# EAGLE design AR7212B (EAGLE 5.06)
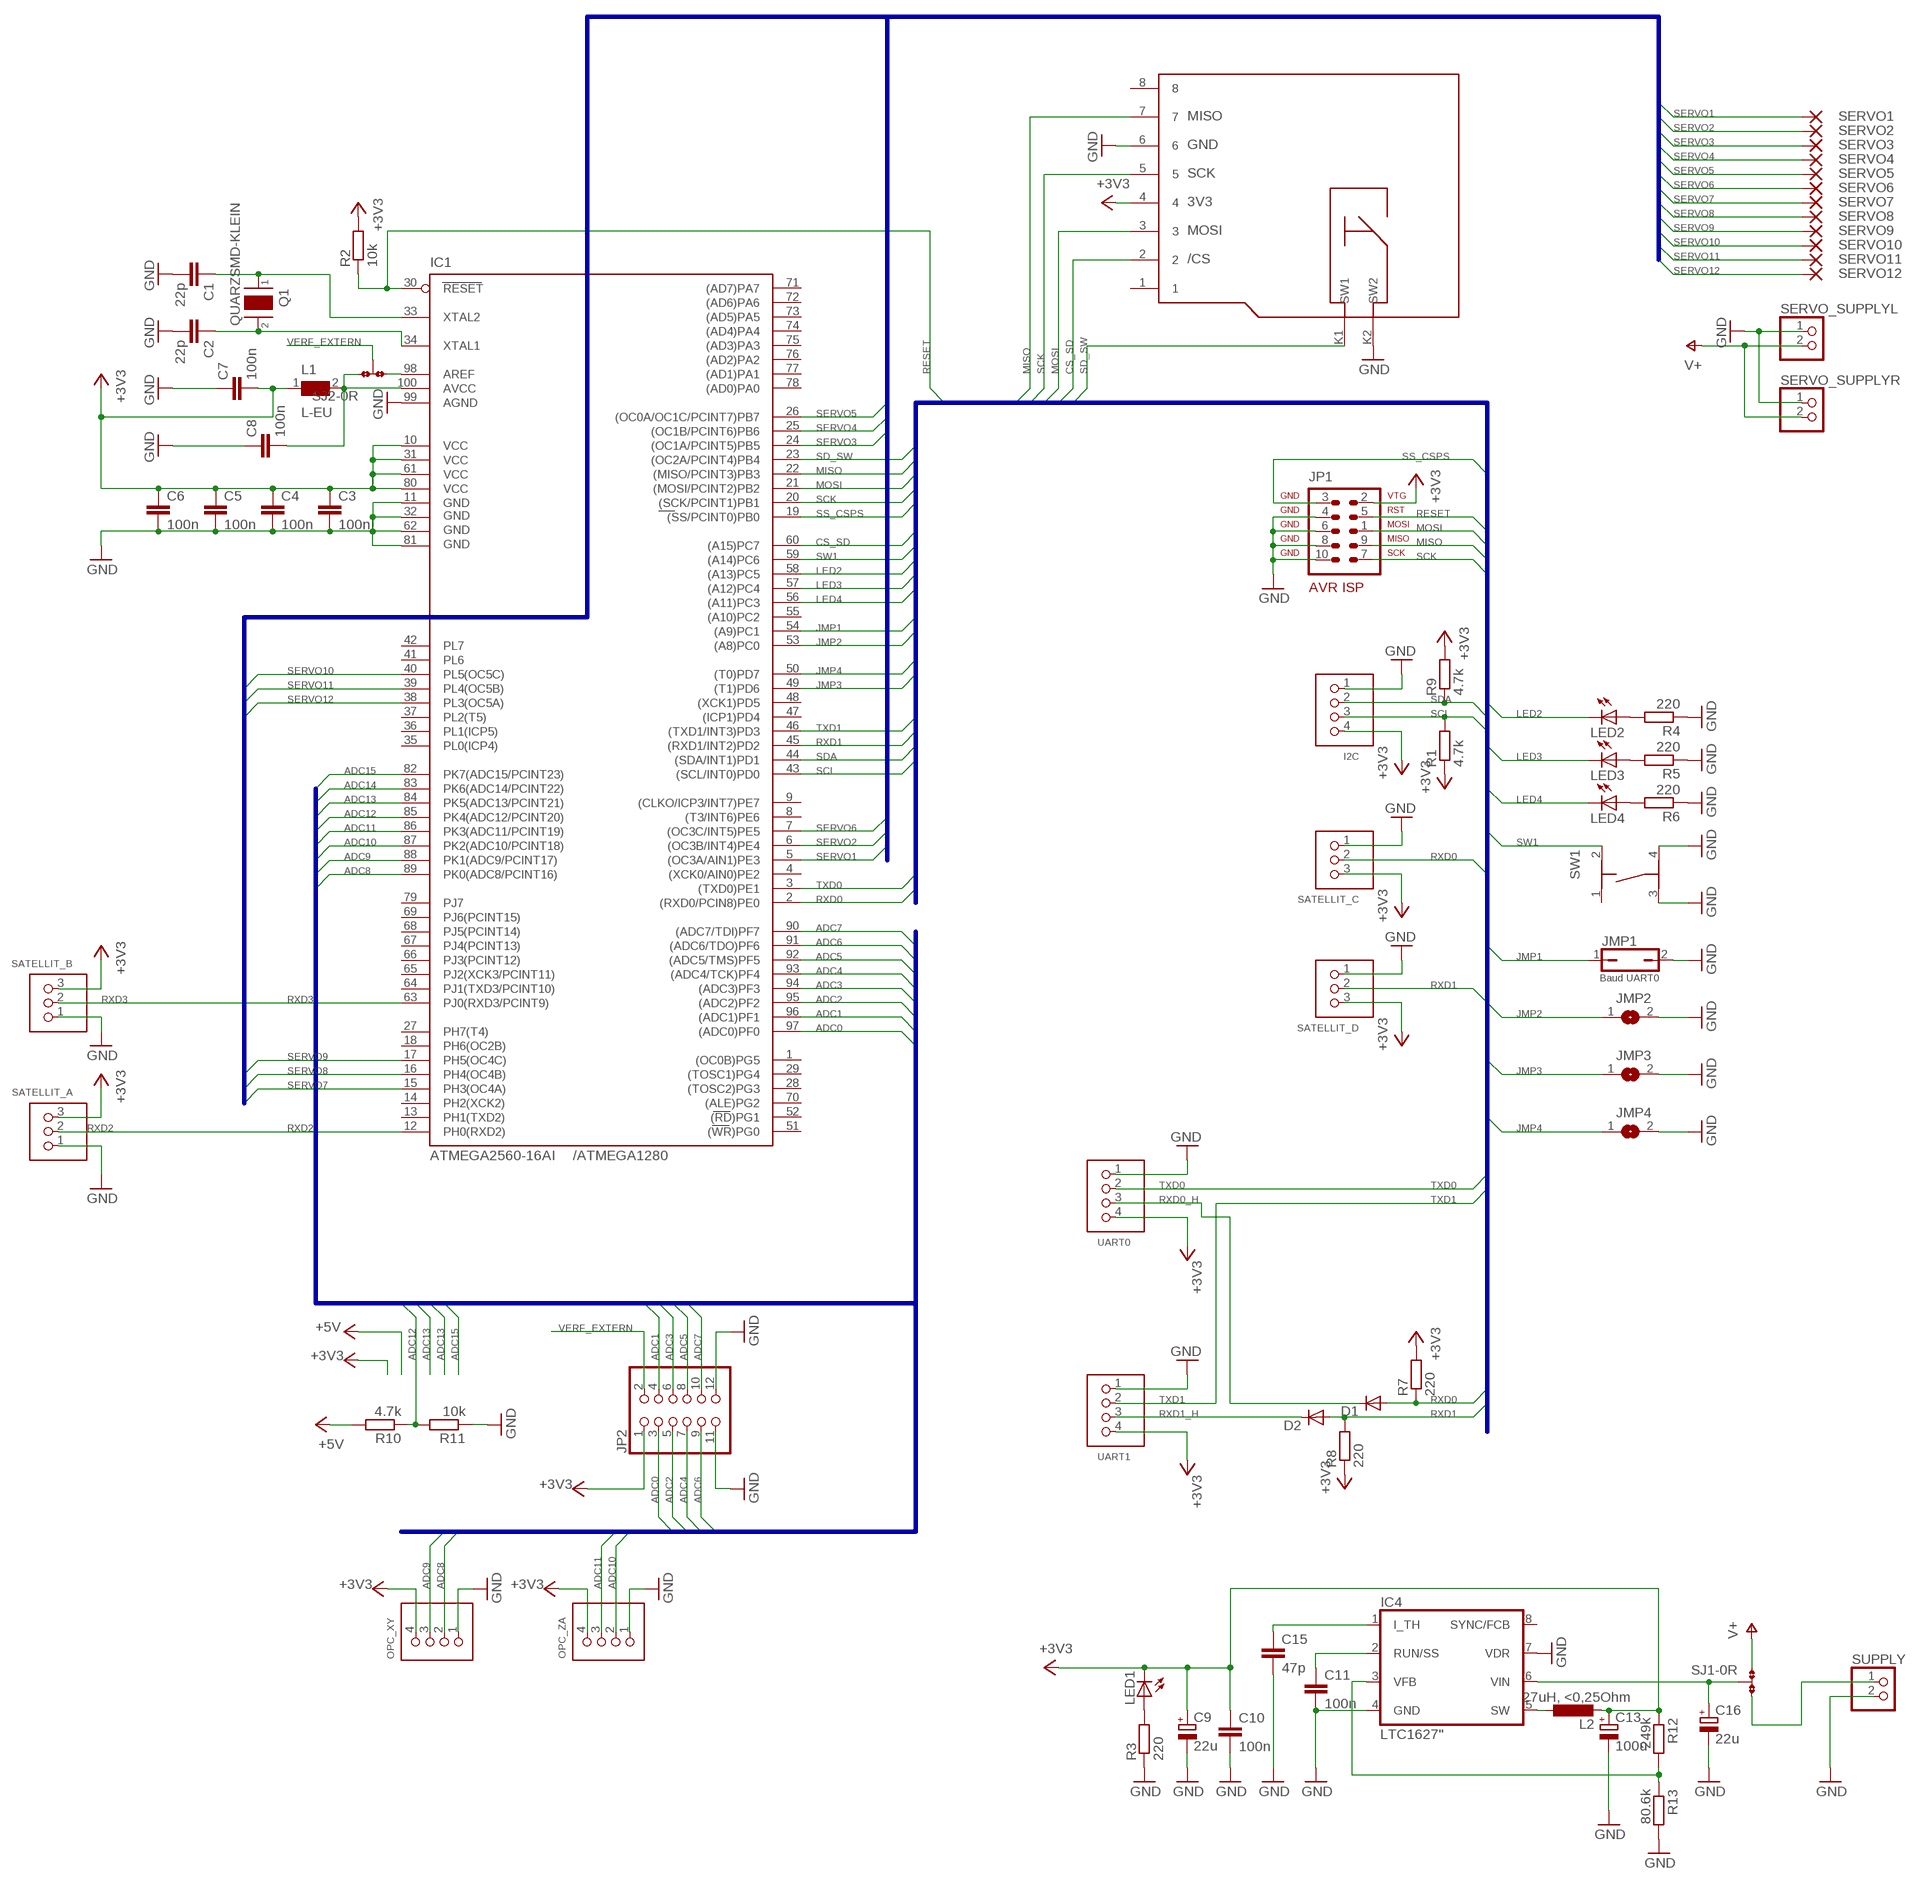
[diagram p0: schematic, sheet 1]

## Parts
C1  22p  C-EUC0805  [C0805]
C2  22p  C-EUC0805  [C0805]
C3  100n  C-EUC0805  [C0805]
C4  100n  C-EUC0805  [C0805]
C5  100n  C-EUC0805  [C0805]
C6  100n  C-EUC0805  [C0805]
C7  100n  C-EUC0805  [C0805]
C8  100n  C-EUC0805  [C0805]
C9  22u  CPOL-EU085CS-1AR  [085CS_1AR]
C10  100n  C-EUC0805  [C0805]
C11  100n  C-EUC0805  [C0805]
C13  100u  CPOL-EU085CS-1AR  [085CS_1AR]
C15  47p  C-EUC0805  [C0805]
C16  22u  CPOL-EU085CS-1AR  [085CS_1AR]
D1  DIODE-MINIMELF  [MINIMELF]
D2  DIODE-MINIMELF  [MINIMELF]
I2C  4PINS  [S4B-ZR-3.4]
IC1  ATMEGA2560-16AI  [TQFP100]
IC4  LTC1627"  [SOIC8]
JMP1  JP1Q  [JP1]
JMP2  SJW  [SJW]
JMP3  SJW  [SJW]
JMP4  SJW  [SJW]
JP1  AVR-ISP-10  [AVR-ISP-10]
JP2  PINHD-2X6  [2X06]
L1  L-EU  [L0805]
L2  27uH, <0,25Ohm  L-EUPIS2816  [PIS2816]
LED1  LEDSMT1206  [1206]
LED2  LEDSMT1206  [1206]
LED3  LEDSMT1206  [1206]
LED4  LEDSMT1206  [1206]
OPC_XY  4PINS  [S4B-ZR-3.4]
OPC_ZA  4PINS  [S4B-ZR-3.4]
Q1  QUARZSMD-KLEIN  [QUARZ_SMD_5X7]
R1  4.7k  R-EU_R0805  [R0805]
R2  10k  R-EU_R0805  [R0805]
R3  220  R-EU_R0805  [R0805]
R4  220  R-EU_R0805  [R0805]
R5  220  R-EU_R0805  [R0805]
R6  220  R-EU_R0805  [R0805]
R7  220  R-EU_R0805  [R0805]
R8  220  R-EU_R0805  [R0805]
R9  4.7k  R-EU_R0805  [R0805]
R10  4.7k  R-EU_R0805  [R0805]
R11  10k  R-EU_R0805  [R0805]
R12  249k  R-EU_R0805  [R0805]
R13  80.6k  R-EU_R0805  [R0805]
SATELLIT_A  3PINS  [S3B-ZR-3.4]
SATELLIT_B  3PINS  [S3B-ZR-3.4]
SATELLIT_C  3PINS  [S3B-ZR-3.4]
SATELLIT_D  3PINS  [S3B-ZR-3.4]
SERVO1  SMD2  [SMD1,27-2,54]
SERVO2  SMD2  [SMD1,27-2,54]
SERVO3  SMD2  [SMD1,27-2,54]
SERVO4  SMD2  [SMD1,27-2,54]
SERVO5  SMD2  [SMD1,27-2,54]
SERVO6  SMD2  [SMD1,27-2,54]
SERVO7  SMD2  [SMD1,27-2,54]
SERVO8  SMD2  [SMD1,27-2,54]
SERVO9  SMD2  [SMD1,27-2,54]
SERVO10  SMD2  [SMD1,27-2,54]
SERVO11  SMD2  [SMD1,27-2,54]
SERVO12  SMD2  [SMD1,27-2,54]
SERVO_SUPPLYL  PINHD-1X2  [1X02]
SERVO_SUPPLYR  PINHD-1X2  [1X02]
SJ1  0R-JUMPA  [A0R-JMP]
SJ2  0R-JUMPB  [B0R-JMP]
SUPPLY  PINHD-1X2  [1X02]
SW1  TASTER-9314_SMD  [TASTER-9314_SMD]
UART0  4PINS  [S4B-ZR-3.4]
UART1  4PINS  [S4B-ZR-3.4]
X2  MICRO-SD  [MICRO-SD]

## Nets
+3V3: C3.1 C4.1 C5.1 C6.1 C7.2 C9.+ C10.1 C13.+ I2C.4 IC1.10(VCC) IC1.31(VCC1) IC1.61(VCC2) IC1.80(VCC3) JP1.2 JP2.1 L1.1 L2.2 LED1.C OPC_XY.4 OPC_ZA.4 R1.1 R2.2 R7.2 R8.1 R9.2 R12.1 SATELLIT_A.3 SATELLIT_B.3 SATELLIT_C.3 SATELLIT_D.3 UART0.4 UART1.4 X2.4
+5V: R10.2
ADC0: IC1.97((ADC0)PF0) JP2.3
ADC1: IC1.96((ADC1)PF1) JP2.4
ADC2: IC1.95((ADC2)PF2) JP2.5
ADC3: IC1.94((ADC3)PF3) JP2.6
ADC4: IC1.93((ADC4/TCK)PF4) JP2.7
ADC5: IC1.92((ADC5/TMS)PF5) JP2.8
ADC6: IC1.91((ADC6/TDO)PF6) JP2.9
ADC7: IC1.90((ADC7/TDI)PF7) JP2.10
ADC8: IC1.89(PK0(ADC8/PCINT16)) OPC_XY.2
ADC9: IC1.88(PK1(ADC9/PCINT17)) OPC_XY.3
ADC10: IC1.87(PK2(ADC10/PCINT18)) OPC_ZA.2
ADC11: IC1.86(PK3(ADC11/PCINT19)) OPC_ZA.3
ADC12: IC1.85(PK4(ADC12/PCINT20)) R10.1 R11.2
ADC13: IC1.84(PK5(ADC13/PCINT21))
ADC14: IC1.83(PK6(ADC14/PCINT22))
ADC15: IC1.82(PK7(ADC15/PCINT23))
AREF: C8.2 IC1.100(AVCC) L1.2 SJ2.3
CS_SD: IC1.60((A15)PC7) X2.2
GND: C1.2 C2.2 C3.2 C4.2 C5.2 C6.2 C7.1 C8.1 C9.- C10.2 C11.2 C13.- C15.2 C16.- I2C.1 IC1.11(GND) IC1.32(GND1) IC1.62(GND2) IC1.81(GND3) IC1.99(AGND) IC4.4(GND) IC4.7(VDR) JMP1.2 JMP2.2 JMP3.2 JMP4.2 JP1.4 JP1.6 JP1.8 JP1.10 JP2.11 JP2.12 OPC_XY.1 OPC_ZA.1 R3.1 R4.1 R5.1 R6.1 R11.1 R13.2 SATELLIT_A.1 SATELLIT_B.1 SATELLIT_C.1 SATELLIT_D.1 SERVO_SUPPLYL.1 SERVO_SUPPLYR.1 SUPPLY.2 SW1.3 SW1.4 UART0.1 UART1.1 X2.6 X2.K2(SW2)
JMP1: IC1.54((A9)PC1) JMP1.1
JMP2: IC1.53((A8)PC0) JMP2.1
JMP3: IC1.49((T1)PD6) JMP3.1
JMP4: IC1.50((T0)PD7) JMP4.1
LED2: IC1.58((A13)PC5) LED2.C
LED3: IC1.57((A12)PC4) LED3.C
LED4: IC1.56((A11)PC3) LED4.C
MISO: IC1.22((MISO/PCINT3)PB3) JP1.9 X2.7
MOSI: IC1.21((MOSI/PCINT2)PB2) JP1.1 X2.3
N$1: LED2.A R4.2
N$2: C15.1 IC4.1(I_TH)
N$3: LED3.A R5.2
N$4: LED4.A R6.2
N$5: IC4.5(SW) L2.1
N$6: IC1.98(AREF) SJ2.1
N$7: C16.+ IC4.6(VIN) SJ1.2
N$9: LED1.A R3.2
N$10: IC4.3(VFB) R12.2 R13.1
RESET: IC1.30(RESET) JP1.5 R2.1
RUN_ISS: C11.1 IC4.2(RUN/SS)
RXD0: D1.A IC1.2((RXD0/PCIN8)PE0) R7.1 SATELLIT_C.2
RXD0_H: D1.C UART0.3
RXD1: D2.A IC1.45((RXD1/INT2)PD2) R8.2 SATELLIT_D.2
RXD1_H: D2.C UART1.3
RXD2: IC1.12(PH0(RXD2)) SATELLIT_A.2
RXD3: IC1.63(PJ0(RXD3/PCINT9)) SATELLIT_B.2
SCK: IC1.20((SCK/PCINT1)PB1) JP1.7 X2.5
SCL: I2C.3 IC1.43((SCL/INT0)PD0) R1.2
SD_SW: IC1.23((OC2A/PCINT4)PB4) X2.K1(SW1)
SDA: I2C.2 IC1.44((SDA/INT1)PD1) R9.1
SERVO1: IC1.5((OC3A/AIN1)PE3) SERVO1.1(P)
SERVO2: IC1.6((OC3B/INT4)PE4) SERVO2.1(P)
SERVO3: IC1.24((OC1A/PCINT5)PB5) SERVO3.1(P)
SERVO4: IC1.25((OC1B/PCINT6)PB6) SERVO4.1(P)
SERVO5: IC1.26((OC0A/OC1C/PCINT7)PB7) SERVO5.1(P)
SERVO6: IC1.7((OC3C/INT5)PE5) SERVO6.1(P)
SERVO7: IC1.15(PH3(OC4A)) SERVO7.1(P)
SERVO8: IC1.16(PH4(OC4B)) SERVO8.1(P)
SERVO9: IC1.17(PH5(OC4C)) SERVO9.1(P)
SERVO10: IC1.40(PL5(OC5C)) SERVO10.1(P)
SERVO11: IC1.39(PL4(OC5B)) SERVO11.1(P)
SERVO12: IC1.38(PL3(OC5A)) SERVO12.1(P)
SS_CSPS: IC1.19((SS/PCINT0)PB0) JP1.3
SUPPLY: SJ1.3 SUPPLY.1
SW1: IC1.59((A14)PC6) SW1.2
TXD0: IC1.3((TXD0)PE1) UART0.2
TXD1: IC1.46((TXD1/INT3)PD3) UART1.2
V+: SERVO_SUPPLYL.2 SERVO_SUPPLYR.2 SJ1.1
VERF_EXTERN: JP2.2 SJ2.2
XTAL1: C2.1 IC1.34(XTAL1) Q1.3
XTAL2: C1.1 IC1.33(XTAL2) Q1.1
Unconnected: IC1.1((OC0B)PG5) IC1.4((XCK0/AIN0)PE2) IC1.8((T3/INT6)PE6) IC1.9((CLKO/ICP3/INT7)PE7) IC1.13(PH1(TXD2)) IC1.14(PH2(XCK2)) IC1.18(PH6(OC2B)) IC1.27(PH7(T4)) IC1.28((TOSC2)PG3) IC1.29((TOSC1)PG4) IC1.35(PL0(ICP4)) IC1.36(PL1(ICP5)) IC1.37(PL2(T5)) IC1.41(PL6) IC1.42(PL7) IC1.47((ICP1)PD4) IC1.48((XCK1)PD5) IC1.51((WR)PG0) IC1.52((RD)PG1) IC1.55((A10)PC2) IC1.64(PJ1(TXD3/PCINT10)) IC1.65(PJ2(XCK3/PCINT11)) IC1.66(PJ3(PCINT12)) IC1.67(PJ4(PCINT13)) IC1.68(PJ5(PCINT14)) IC1.69(PJ6(PCINT15)) IC1.70((ALE)PG2) IC1.71((AD7)PA7) IC1.72((AD6)PA6) IC1.73((AD5)PA5) IC1.74((AD4)PA4) IC1.75((AD3)PA3) IC1.76((AD2)PA2) IC1.77((AD1)PA1) IC1.78((AD0)PA0) IC1.79(PJ7) IC4.8(SYNC/FCB) SW1.1 X2.1 X2.8

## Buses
I/O:MISO,MOSI,SCK,RESET,VTG,SS_CSPS,CS_SD,SD_SW,LED2,LED3,LED4,SW1,JMP1,JMP2,JMP3,JMP4,RXD0,TXD0,RXD1,TXD1,SCL,SDA
SERVO:SERVO1,SERVO2,SERVO3,SERVO4,SERVO5,SERVO6,SERVO7,SERVO8,SERVO9,SERVO10,SERVO11,SERVO12
ADC_INPUT:ADC0,ADC1,ADC2,ADC3,ADC4,ADC5,ADC6,ADC7,ADC8,ADC9,ADC10,ADC11,ADC12,ADC13,ADC14,ADC15

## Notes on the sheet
- Baud UART0
- /ATMEGA1280

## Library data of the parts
C1-C8 C10 C11 C15 = rcl:C-EU: CAPACITOR, European symbol
C9 C13 C16 = rcl:CPOL-EU: POLARIZED CAPACITOR, European symbol
D1 D2 = diode:DIODE-: DIODE
I2C OPC_XY OPC_ZA UART0 UART1 = rcos:4PIN
IC1 = rcos:ATMEGA*: MICROCONTROLLER 64/128/256 Kbytes FLASH 4 Kbytes EEPROM 8 Kbytes SRAM 86 General Purpose I/O pins 12-channels16-bit PWM 4 x Serial USARTs 16-channels 10-bit A/D
IC4 = rcos:LTC1627: 3V Micropower Sampling 12-Bit A/D Converters Source: http://www.linear.com/pc/downloadDocument.do?navId=H0,C1,C1155,C1001,C1158,P1489,D3463
JMP1 = jumper:JP1Q: JUMPER
JMP2-JMP4 = jumper:SJ: SMD solder JUMPER
JP1 = avr-5:AVR-ISP-10: AVR ISP-10 Serial Programming Header
JP2 = pinheadRound:PINHD-2X6: PIN HEADER
L1 = rcos:L-EU: SMD Induktivität
L2 = rcl:L-EU: INDUCTOR, European symbol
LED1-LED4 = led:LED: LED
Q1 = rcos:QUARZ: Schwingquarz
R1-R13 = rcl:R-EU_: RESISTOR, European symbol
SATELLIT_A SATELLIT_B SATELLIT_C SATELLIT_D = rcos:3PIN
SERVO1-SERVO12 = wirepad:SMD2: SMD PAD
SERVO_SUPPLYL SERVO_SUPPLYR SUPPLY = pinheadRound:PINHD-1X2: PIN HEADER
SJ1 SJ2 = jump-0r-smd:0R-JUMP: SMD 0R 0805 Jumper
SW1 = rcos:TASTER-9314_SMD
X2 = rcos:MICRO-SD

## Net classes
0 default: width 0.152 mm, drill 0.305 mm, clearance 0.152 mm

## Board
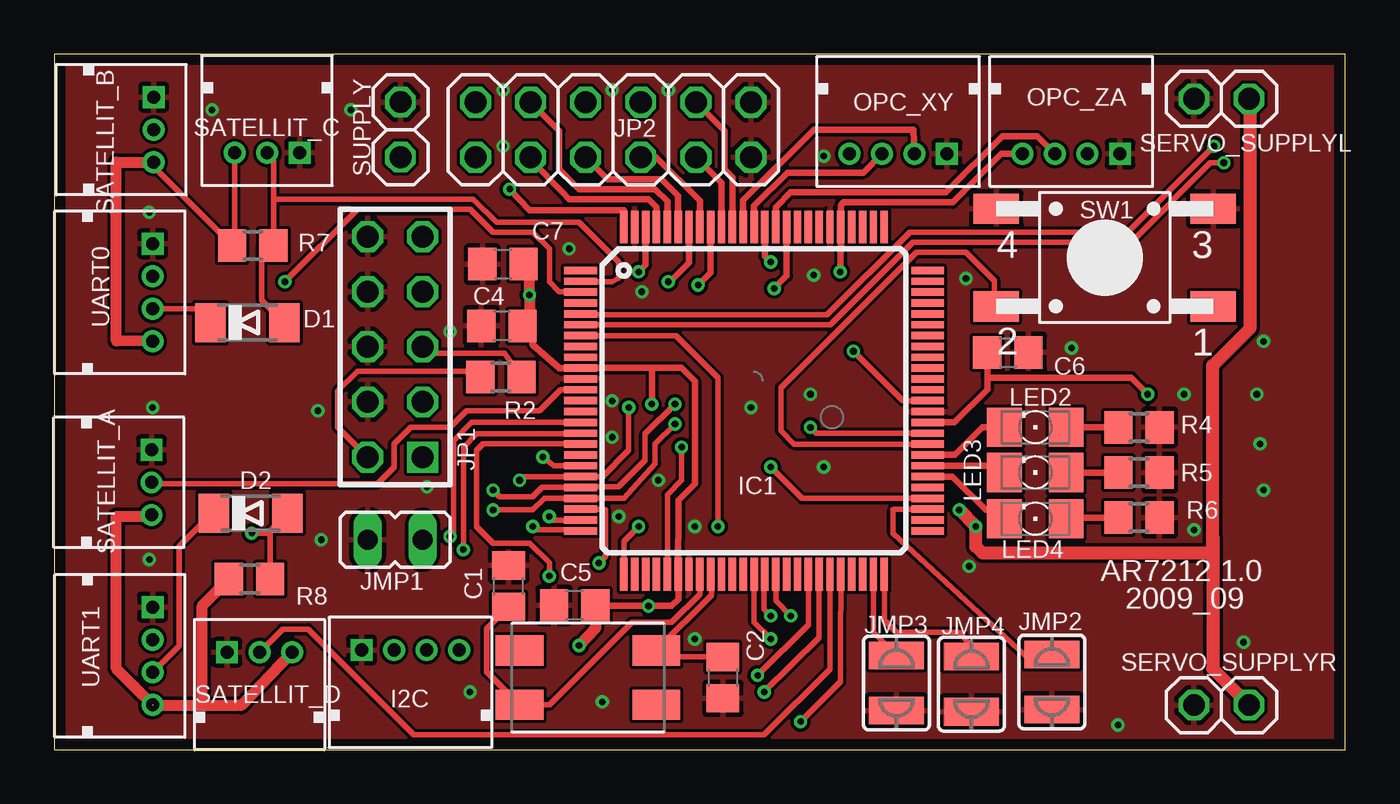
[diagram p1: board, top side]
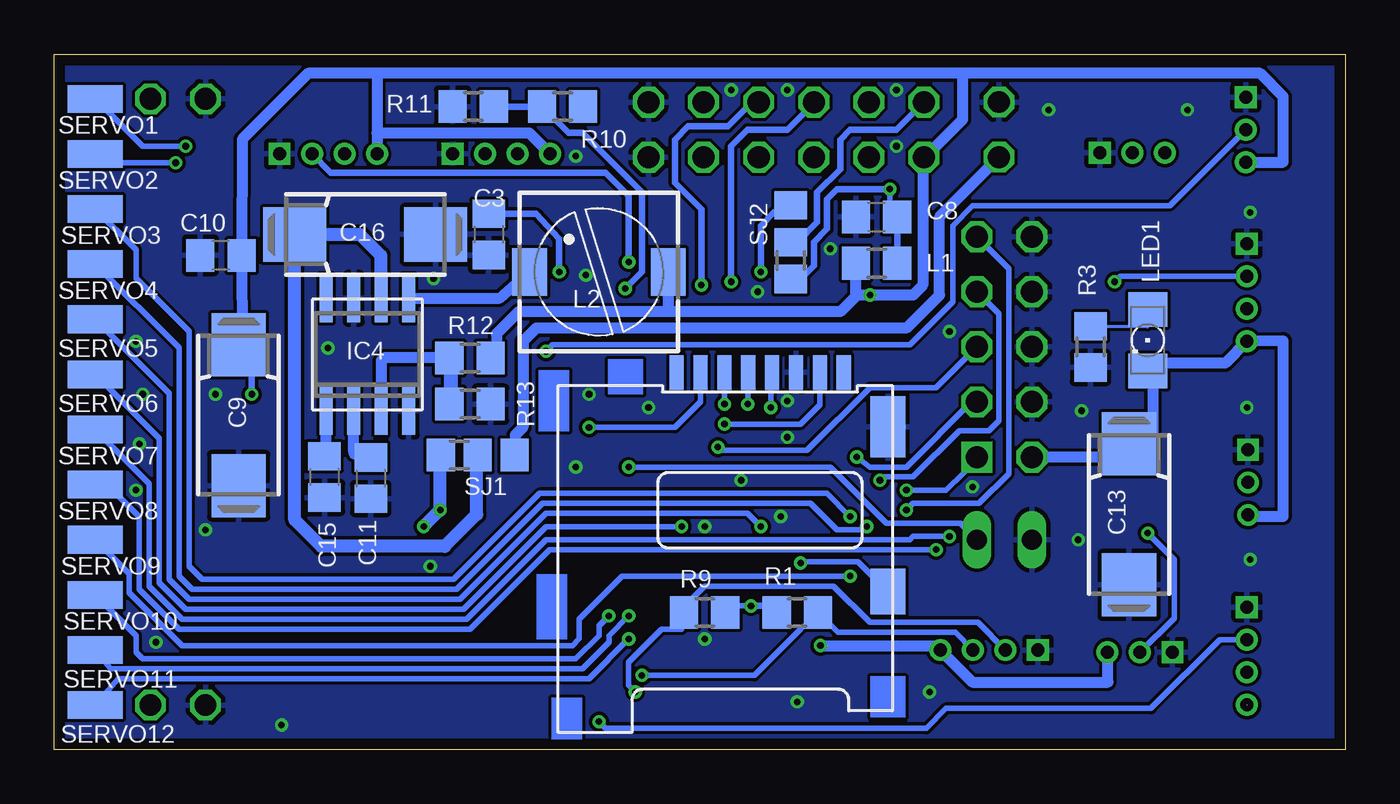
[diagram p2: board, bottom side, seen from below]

Size 59.51 x 32.04 mm. Coordinates in mm from the lower left corner, seen from the top.
Outline: 0,0 59.51,0 59.51,32.04 0,32.04 0,0
Copper layers (1*16): Top 0.035mm / dielectric 1.5mm / Bottom 0.035mm
Design rules "PCB-POOL": minimum track width 6mil, minimum drill 12mil, track to track 6mil, track to pad 6mil, pad to pad 6mil, via to via 6mil, smd to smd 6mil, copper to edge 20mil, drill to drill 8mil, minimum pad ring 8mil, minimum via ring 6mil, stop-mask expansion 3mil, vias tented up to drill 0mil, thermal gap 8mil

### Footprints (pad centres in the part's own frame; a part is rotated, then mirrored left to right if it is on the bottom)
C0805 = smd 1.3 x 1.5: 1 -0.95,0; 2 0.95,0
085CS_1AR = smd 2.9 x 2.5: + 3.25,0; - -3.25,0
MINIMELF = smd 1.4 x 1.8: A 1.7,0; C -1.7,0
S4B-ZR-3.4 = drill 0.6 square: 1 2.23,0 | drill 0.6 round: 2 0.73,0; 3 -0.77,0; 4 -2.27,0
TQFP100 = smd 1.5 x 0.34: 1 -8,6; 2 -8,5.5; 3 -8,5; 4 -8,4.5; 5 -8,4; 6 -8,3.5; 7 -8,3; 8 -8,2.5; 9 -8,2; 10 -8,1.5; 11 -8,1; 12 -8,0.5; 13 -8,0; 14 -8,-0.5; 15 -8,-1; 16 -8,-1.5; 17 -8,-2; 18 -8,-2.5; 19 -8,-3; 20 -8,-3.5; 21 -8,-4; 22 -8,-4.5; 23 -8,-5; 24 -8,-5.5; 25 -8,-6; 51 8,-6; 52 8,-5.5; 53 8,-5; 54 8,-4.5; 55 8,-4; 56 8,-3.5; 57 8,-3; 58 8,-2.5; 59 8,-2; 60 8,-1.5; 61 8,-1; 62 8,-0.5; 63 8,0; 64 8,0.5; 65 8,1; 66 8,1.5; 67 8,2; 68 8,2.5; 69 8,3; 70 8,3.5; 71 8,4; 72 8,4.5; 73 8,5; 74 8,5.5; 75 8,6 | smd 0.34 x 1.5: 26 -6,-8; 27 -5.5,-8; 28 -5,-8; 29 -4.5,-8; 30 -4,-8; 31 -3.5,-8; 32 -3,-8; 33 -2.5,-8; 34 -2,-8; 35 -1.5,-8; 36 -1,-8; 37 -0.5,-8; 38 0,-8; 39 0.5,-8; 40 1,-8; 41 1.5,-8; 42 2,-8; 43 2.5,-8; 44 3,-8; 45 3.5,-8; 46 4,-8; 47 4.5,-8; 48 5,-8; 49 5.5,-8; 50 6,-8; 76 6,8; 77 5.5,8; 78 5,8; 79 4.5,8; 80 4,8; 81 3.5,8; 82 3,8; 83 2.5,8; 84 2,8; 85 1.5,8; 86 1,8; 87 0.5,8; 88 0,8; 89 -0.5,8; 90 -1,8; 91 -1.5,8; 92 -2,8; 93 -2.5,8; 94 -3,8; 95 -3.5,8; 96 -4,8; 97 -4.5,8; 98 -5,8; 99 -5.5,8; 100 -6,8
SOIC8 = smd 0.6 x 2.2: 1 -1.905,-2.6; 2 -0.635,-2.6; 3 0.635,-2.6; 4 1.905,-2.6; 5 1.905,2.6; 6 0.635,2.6; 7 -0.635,2.6; 8 -1.905,2.6
JP1 = drill 0.914 long: 1 0,-1.27; 2 0,1.27
SJW = smd 1.27 x 2.54: 1 -1.27,0; 2 1.27,0
AVR-ISP-10 = drill 1.016 square: 1 -5.08,-1.27 | drill 1.016 octagon: 2 -5.08,1.27; 3 -2.54,-1.27; 4 -2.54,1.27; 5 0,-1.27; 6 0,1.27; 7 2.54,-1.27; 8 2.54,1.27; 9 5.08,-1.27; 10 5.08,1.27
2X06 = drill 1.016 octagon: 1 -6.35,-1.27; 2 -6.35,1.27; 3 -3.81,-1.27; 4 -3.81,1.27; 5 -1.27,-1.27; 6 -1.27,1.27; 7 1.27,-1.27; 8 1.27,1.27; 9 3.81,-1.27; 10 3.81,1.27; 11 6.35,-1.27; 12 6.35,1.27
L0805 = smd 1.3 x 1.5: 1 -0.95,0; 2 0.95,0
PIS2816 = smd 2.2 x 1.6: 1 0,3.2; 2 0,-3.2
1206 = smd 1.6 x 1.803: A -1.422,0; C 1.422,0
QUARZ_SMD_5X7 = smd 2.2 x 1.4: 1 -3.15,-1.25; 2 3.15,-1.25; 3 3.15,1.25; 4 -3.15,1.25
R0805 = smd 1.3 x 1.5: 1 -0.95,0; 2 0.95,0
S3B-ZR-3.4 = drill 0.6 square: 1 1.5,0 | drill 0.6 round: 2 0,0; 3 -1.5,0
SMD1,27-2,54 = smd 1.27 x 2.54: 1 0,0
1X02 = drill 1 octagon: 1 -1.27,0; 2 1.27,0
A0R-JMP = smd 1.5 x 1.3: 1 0,1.7; 2 0,0; 3 0,-1.7
B0R-JMP = smd 1.5 x 1.3: 1 0,1.7; 2 0,0; 3 0,-1.7
TASTER-9314_SMD = smd 2.1 x 1.4: 1 -5,2.25; 2 5,2.25; 3 -5,-2.25; 4 5,-2.25
MICRO-SD = smd 0.65 x 1.6: 1 -10.54,16.6; 2 -9.44,16.6; 3 -8.34,16.6; 4 -7.24,16.6; 5 -6.14,16.6; 6 -5.04,16.6; 7 -3.94,16.6; 8 -2.84,16.6 | smd 1.6 x 2.1: K1 -0.8,6.5 | smd 1.6 x 2.8: K2 -0.8,14.1

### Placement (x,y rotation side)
C1  20.94,7.54 90 top
C2  30.82,3.32 270 top
C3  39.48,23.74 270 bottom
C4  20.64,19.53 180 top
C5  23.99,6.65 180 top
C6  43.95,18.31 0 top
C7  20.69,22.38 0 top
C8  21.6,24.55 0 bottom
C9  51.02,15.41 90 bottom
C10  51.83,22.78 180 bottom
C11  44.92,12.52 270 bottom
C13  9.97,10.84 90 bottom
C15  47.05,12.57 270 bottom
C16  45.17,23.74 180 bottom
D1  8.9,19.68 0 top
D2  9.06,10.89 0 top
I2C  16.4,4.59 180 top
IC1  32.26,16.08 0 top
IC4  45.07,18.21 0 bottom
JMP1  15.71,9.67 90 top
JMP2  45.99,3.12 270 top
JMP3  38.82,3.07 270 top
JMP4  42.28,3.02 270 top
JP1  15.71,18.56 90 top
JP2  25.77,28.57 0 top
L1  21.6,22.42 0 bottom
L2  34.4,22.02 90 bottom
LED1  9.11,18.87 270 bottom
LED2  45.22,14.85 180 top
LED3  45.22,12.77 180 top
LED4  45.22,10.64 180 top
OPC_XY  38.93,27.45 0 top
OPC_ZA  46.9,27.45 0 top
Q1  24.6,3.32 0 top
R1  25.26,6.32 0 bottom
R2  20.59,17.17 180 top
R3  11.75,18.56 90 bottom
R4  50,14.85 180 top
R5  50,12.77 180 top
R6  50,10.69 180 top
R7  9.16,23.24 180 top
R8  9,7.87 0 top
R9  29.53,6.32 0 bottom
R10  36.08,29.64 0 bottom
R11  40.2,29.64 0 bottom
R12  40.35,18.05 180 bottom
R13  40.35,15.92 0 bottom
SATELLIT_A  4.48,12.31 90 top
SATELLIT_B  4.58,28.57 90 top
SATELLIT_C  9.82,27.5 0 top
SATELLIT_D  9.46,4.49 180 top
SERVO1  57.62,29.99 90 bottom
SERVO2  57.62,27.45 90 bottom
SERVO3  57.62,24.91 90 bottom
SERVO4  57.62,22.37 90 bottom
SERVO5  57.62,19.83 90 bottom
SERVO6  57.62,17.29 90 bottom
SERVO7  57.62,14.75 90 bottom
SERVO8  57.62,12.21 90 bottom
SERVO9  57.62,9.67 90 bottom
SERVO10  57.62,7.13 90 bottom
SERVO11  57.62,4.59 90 bottom
SERVO12  57.62,2.05 90 bottom
SERVO_SUPPLYL  53.81,29.99 0 top
SERVO_SUPPLYR  53.81,2.05 0 top
SJ1  39.99,13.58 90 bottom
SJ2  25.57,23.39 0 bottom
SUPPLY  15.96,28.57 90 top
SW1  48.43,22.68 180 top
UART0  4.53,21.09 90 top
UART1  4.53,4.34 90 top
X2  20.28,0.78 0 bottom

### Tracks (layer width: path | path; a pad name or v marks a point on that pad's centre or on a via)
+3V3  (via drill 0.3)  (1 unrouted)
  Top 0.152: IC1.31 | 25.57,6.62 C5.1 | IC1.10 24.28,17.6 | C4.1 21.84,19.43 21.91,19.43 | 19.76,17.44 R2.2
  Top 0.254: 19.76,17.44 13.98,17.44 13.07,16.53 13.07,14.85 JP1.2 | SATELLIT_B.3 4.53,26.87 4.88,26.56 R7.2 8.32,23.35 SATELLIT_C.3
  Top 0.305: IC1.10 23.26,17.58 23.28,17.6 22.06,18.66 22.06,19.43 | IC1.31 28.77,6.93 28.46,6.62 v27.39,6.62 25.57,6.62 | 27.55,17.6 v27.55,15.92 | 21.91,19.43 | 21.91,19.43 22.06,19.43 | 22.06,19.43 | IC1.31 28.76,9.53 28.77,9.82 28.77,11.5 29.53,12.26 29.53,16.99 28.92,17.6 27.55,17.6 | 24.28,17.6 27.55,17.6 | OPC_ZA.4 43.65,27.45 41.42,25.22 36.39,25.22 36.26,25.09 IC1.80 36.26,22.96 36.23,22.93 v36.23,22.02 | IC1.61 41.49,15.08 43,16.6 43,17.14 | 43,17.14 C6.1 | v50.41,16.38 49.64,17.14 43,17.14
  Top 0.508: 21.91,19.43 v21.91,20.95 21.91,22.38 C7.2 | v24.19,4.8 24.96,5.6 C5.1 | UART0.4 2.86,18.83 2.86,27.07 SATELLIT_B.3 | 8.61,2.03 10.89,4.42 SATELLIT_D.3 | UART1.4 3.7,2.91 3.7,2.89 2.86,3.73 2.86,10.76 4.48,10.76 SATELLIT_A.3 | 4.53,2.05 6.82,2.05 | 6.82,2.05 8.5,2.05 | R8.1 6.82,6.63 6.82,2.05
  Bottom 0.152: 22.97,22.47 22.97,22.07 | R1.1 26.33,6.89 | 39.47,17.71 39.47,18.32
  Bottom 0.254: R9.2 28.27,6.62 v27.39,6.62 | C13.+ 10.17,13.48 | 22.97,22.47 22.97,22.63 22.82,22.78 | X2.4 27.52,15.95 v27.55,15.92
  Bottom 0.305: v27.39,6.62 26.33,6.62 26.33,6.44 R1.1 | 50.85,18.65 50.41,18.21 v50.41,16.38 | C3.1 37.3,24.69 36.23,23.54 v36.23,22.02
  Bottom 0.508: v24.19,4.8 18.68,4.8 18.62,4.73 18.67,4.68 I2C.4 17.19,3.11 10.94,3.11 10.94,4.47 SATELLIT_D.3 | 22.52,20.95 v21.91,20.95 19.93,20.95 19.47,21.41 19.47,26.74 19.37,27.15 JP2.1 19.21,27.45 17.64,29.03 17.64,31.16 | 22.52,20.95 22.55,20.99 L1.1 22.76,22.63 22.82,22.78 | R12.1 39.47,17.71 39.13,17.75 39.13,19.16 38.1,20.19 31.2,20.19 | 17.64,31.16 3.92,31.16 2.86,30.09 2.86,27.07 SATELLIT_B.3 | 17.64,31.16 44.61,31.16 | 44.61,31.16 47.82,31.16 50.85,28.13 C10.1 50.85,18.65 C9.+ | 44.63,28.42 44.63,30.99 44.61,31.16 | 44.63,28.42 OPC_ZA.4 | JP1.2 10.17,13.48 8.87,13.48 8.87,16.9 LED1.C 8.43,17.82 5.53,17.82 UART0.4 2.86,18.83 2.86,10.76 4.48,10.76 SATELLIT_A.3 | 22.52,20.95 23.28,20.19 31.2,20.19 | OPC_XY.4 37.62,28.42 44.63,28.42 | 31.2,20.19 L2.2
ADC0
  Top 0.305: IC1.97 27.76,25 27.39,25.37 23.74,25.37 23.43,25.67 22.06,27.1 JP2.3
ADC1
  Top 0.305: IC1.96 28.26,25.27 27.7,25.83 24.19,25.83 23.28,26.74 23.28,28.52 JP2.4
ADC2
  Top 0.305: IC1.95 28.76,25.53 28,26.28 25.51,26.28 JP2.5
ADC3  (via drill 0.3)
  Top 0.254: 28.38,21.56 v28.31,21.56
  Top 0.305: IC1.94 29.26,22.44 28.38,21.56
  Bottom 0.305: v28.31,21.56 28.31,27.81 27.55,28.57 25.72,28.57 24.5,29.79 JP2.6
ADC4
  Top 0.305: IC1.93 29.76,25.29 27.75,27.3 JP2.7
ADC5  (via drill 0.3)
  Top 0.305: IC1.92 30.26,21.99 v29.68,21.41
  Bottom 0.305: v29.68,21.41 29.68,24.91 30.9,26.13 30.9,28.11 30.29,28.72 28.46,28.72 27.34,29.84 JP2.8
ADC6
  Top 0.305: IC1.91 30.76,26.12 JP2.9
ADC7
  Top 0.305: IC1.90 31.26,26.38 30.9,26.74 30.9,28.52 JP2.10
ADC8
  Top 0.305: IC1.89 31.76,25.32 35.01,28.57 39.61,28.57 OPC_XY.2
ADC9
  Top 0.305: IC1.88 32.26,25.05 33.8,26.59 37.29,26.59 OPC_XY.3
ADC10  (via drill 0.3)
  Top 0.305: IC1.87 32.76,22.75 v33.03,22.47
  Bottom 0.305: v33.03,22.47 33.03,25.52 34.1,26.59 46.77,26.59 OPC_ZA.2
ADC11
  Top 0.305: IC1.86 33.26,24.99 33.95,25.67 41.11,25.67 43.7,28.27 45.32,28.27 OPC_ZA.3
ADC12  (via drill 0.3)
  Top 0.305: IC1.85 33.76,21.83 v33.19,21.25
  Bottom 0.305: R11.2 R10.1 35.81,28.42 35.17,28.42 32.42,25.67 32.42,22.02 v33.19,21.25
AREF  (via drill 0.3)
  Top 0.305: IC1.100 26.26,24.85 21.91,24.85 v20.99,25.83
  Bottom 0.254: C8.2 20.96,24.76 v20.99,25.83
  Bottom 0.305: C8.2 L1.2 | SJ2.3 25.41,21.56 25.24,21.56 24.5,22.3 24.5,23.39 23.89,24 23.89,25.37 23.43,25.83 v20.99,25.83
CS_SD  (via drill 0.3)
  Top 0.254: IC1.60 35.13,14.58 v34.86,14.85
  Bottom 0.254: v34.86,14.85 30.9,14.85 29.72,16.03 X2.2
GND  (via drill 0.3)
  other vias: 29.53,5.1 34.86,16.38 32.12,15.77 25.72,16.07 49.03,1.14 26.02,10.74 29.53,10.28 27.85,12.42 18.25,19.27 35.01,21.86 27.09,21.1 35.47,13.03 25.26,2.2 19.16,2.66 55.44,16.38 55.59,14.09 55.74,18.82 55.74,11.96 54.83,4.95 17.18,12.11 25.72,14.4 12.15,15.62 12.31,9.67 4.38,8.76 4.53,15.77 4.38,24.76 7.28,29.48 13.68,29.48 20.69,27.81 28.31,30.4 20.69,30.4 25.72,30.4 35.47,27.35 52.54,10.13 42.18,8.45 46.9,18.51 52.08,16.38 42.02,21.71 23.74,23.08
  pour Bottom: -0.8,32.53 -0.8,-0.31 60.16,-0.31 60.16,32.53
  pour Top: -0.8,32.53 -0.8,-0.31 60.16,-0.31 60.16,32.53
JMP1  (via drill 0.3)
  Top 0.254: IC1.54 34.48,11.58 v33.03,13.03
  Bottom 0.254: v33.03,13.03 23.74,13.03 21.15,10.43 17.74,10.43 JMP1.1
JMP2
  Top 0.254: JMP2.1 46.04,4.34 44.77,4.34 38.98,9.67 38.67,9.98 38.67,11.04 38.71,11.08 IC1.53
JMP3
  Top 0.254: IC1.49 37.76,5.4 JMP3.1
JMP4
  Top 0.254: IC1.50 38.26,5.97 38.82,5.41 41.72,5.41 42.23,4.8 JMP4.1
LED2
  Top 0.305: IC1.58 41.52,13.58 42.79,14.85 LED2.C
LED3
  Top 0.305: IC1.57 43.49,13.08 LED3.C
LED4
  Top 0.305: IC1.56 41.4,12.58 42.94,11.04 43.4,11.04 LED4.C
MISO  (via drill 0.3)
  Top 0.254: v28.61,15.01 27.7,14.09 27.7,13.18 26.26,11.58 IC1.22 22.6,11.58 22.06,11.04 v20.23,11.04
  Bottom 0.152: X2.7 24.19,17.41
  Bottom 0.254: v28.61,15.01 25.11,15.01 24.22,15.89 X2.7 | JP1.9 15.51,22.17 15.51,12.72 16.88,11.35 19.93,11.35 v20.23,11.04
MOSI  (via drill 0.3)
  Top 0.152: 24.8,12.11 24.98,12.08 IC1.21
  Top 0.254: 24.8,12.11 26.02,12.11 27.24,13.33 27.24,14.55 v28.61,15.92 | IC1.21 22.49,12.08 22.06,11.65 20.54,11.65 v20.23,11.96
  Bottom 0.152: X2.3
  Bottom 0.254: v28.61,15.92 X2.3 | v20.23,11.96 18.4,11.96 17.59,12.77 JP1.1
N$1
  Top 0.305: LED2.A R4.2
N$2
  Bottom 0.508: C15.1 46.98,13.59 IC4.1
N$3
  Top 0.305: LED3.A R5.2
N$4
  Top 0.305: LED4.A 46.7,10.69 R6.2
N$5
  Bottom 0.508: IC4.5 38.98,20.81 L2.1
N$6  (via drill 0.3)
  Top 0.305: v26.94,22.02 27.26,22.34 IC1.98
  Bottom 0.152: 25.89,24.76 SJ2.1
  Bottom 0.305: 25.89,24.76 26.33,24.76 26.94,24.15 v26.94,22.02
N$7
  Bottom 0.508: 44.46,20.83 IC4.6 | C16.+ 47.82,23.13
  Bottom 0.61: 44.46,20.83 44.46,22.78 45.43,23.74 C16.+ | 47.82,23.13 47.82,23.69 48.42,23.08 48.42,10.59 47.21,9.37 41.52,9.37 40.04,10.84 40.04,13.03 SJ1.2
N$9
  Bottom 0.152: LED1.A 9.12,19.49 R3.2
N$10
  Bottom 0.508: R12.2 41.15,18.36 41.15,16.07 R13.1 R12.2 | R12.2 44.31,18.05 44.44,17.93 IC4.3
RESET  (via drill 0.3)
  Top 0.254: R2.1 20.75,18.26 17.29,18.26 JP1.5 | IC1.30 28.26,11.76 28.92,12.42 v28.92,13.94
  Bottom 0.254: JP1.5 18.86,16.68 21.91,16.68 24.8,13.79 28.77,13.79 v28.92,13.94
RUN_ISS
  Bottom 0.508: C11.1 45.68,13.65 45.68,13.63 45.71,13.81 IC4.2
RXD0
  Top 0.152: 24.24,21.56 IC1.2 | 10.11,23 R7.1 9.56,23.24
  Top 0.254: 24.24,21.56 25.72,21.56 26.02,21.71 26.02,22.47 24.19,24.3 20.38,24.3 19.32,25.37 10.11,25.37 | D1.A 9.56,20.72 9.56,23.24 | 10.11,23 10.11,25.37 | 10.11,25.37 10.11,27.21 SATELLIT_C.2
RXD0_H
  Top 0.254: UART0.3 7.18,20.32 D1.C
RXD1  (via drill 0.3)
  Top 0.152: D2.A 10.72,10.89
  Top 0.254: IC1.45 35.76,3.71 32.73,0.68 16.57,0.68 11.7,5.56 10.53,5.56 SATELLIT_D.2 | D2.A 9.95,10.09 9.95,9.98 | 9.95,9.98 R8.2 | v9.11,9.98 9.95,9.98
  Bottom 0.254: SATELLIT_D.2 7.89,6.07 7.89,8.76 v9.11,9.98
RXD1_H
  Top 0.152: 6.97,10.59 7.28,10.89 D2.C
  Top 0.254: UART1.3 5.75,4.79 5.75,8.45 5.75,9.37 6.97,10.59
RXD2
  Top 0.254: SATELLIT_A.2 4.53,12.26 14.9,12.26 15.66,13.03 15.66,14.09 16.42,14.85 18.25,14.85 19.01,15.62 22.36,15.62 23.33,16.58 IC1.12
RXD3  (via drill 0.3)
  Top 0.254: IC1.63 39.12,16.08 v36.84,18.36
  Bottom 0.254: v36.84,18.36 36.54,18.66 20.08,18.66 18.1,20.65 18.1,24.15 17.18,25.06 8.09,25.06 SATELLIT_B.2
SCK  (via drill 0.3)
  Top 0.254: v26.48,15.77 26.48,13.79 25.28,12.58 IC1.20 24.25,12.57 21.6,12.57 v21.45,12.42
  Bottom 0.152: 26.48,17.32 X2.5
  Bottom 0.254: v26.48,15.77 26.48,17.32 | JP1.7 15.96,20.09 15.96,15.16 16.42,14.7 17.79,14.7 19.93,12.57 21.3,12.57 v21.45,12.42
SCL  (via drill 0.3)
  Top 0.254: IC1.43 34.76,5.76 v32.42,3.42
  Bottom 0.254: v32.42,3.42 27.24,3.42 25.11,5.56 24.5,6.13 R1.2 23.4,5.41 17.98,5.41 I2C.3
SD_SW  (via drill 0.3)
  Top 0.254: v25.11,8.61 25.41,8.91 25.41,11.04 25.22,11.08 IC1.23
  Bottom 0.152: X2.K1 21.3,7.5
  Bottom 0.254: v25.11,8.61 24.85,8.65 22.45,8.65 X2.K1
SDA  (via drill 0.3)
  Top 0.254: v32.73,2.66 35.26,5.16 IC1.44
  Bottom 0.152: 30.59,6.78 R9.1 30.44,6.81
  Bottom 0.254: v32.73,2.66 33.03,2.97 33.03,4.03 31.51,5.56 30.59,5.56 30.59,6.78 | I2C.2 16.94,5.86 21.91,5.86 23.58,7.54 29.53,7.54 30.25,6.81 30.44,6.81
SERVO1  (via drill 0.3)
  Top 0.152: IC1.5 24.31,20.04
  Top 0.254: 24.31,20.04 35.62,20.04 39.43,23.85 49.49,23.85 v53.45,27.81
  Bottom 0.152: SERVO1.1 57.57,29.94
  Bottom 0.254: v53.45,27.81 55.44,27.81 SERVO1.1
SERVO2  (via drill 0.3)
  Top 0.254: IC1.6 35.78,19.58 39.59,23.39 49.64,23.39 53.3,27.05 v53.91,27.05
  Bottom 0.254: 57.06,27.15 SERVO2.1 57.21,27.05 v53.91,27.05
SERVO3  (via drill 0.3)
  Top 0.254: IC1.24 22.98,10.58 v22.82,10.74
  Bottom 0.152: 57.57,24.91 SERVO3.1 57.62,24.81
  Bottom 0.254: v22.82,10.74 23.89,11.81 37.15,11.81 41.11,7.84 52.69,7.84 53.3,8.45 53.3,19.27 55.74,21.71 55.74,23.03 SERVO3.1 57.57,24.86
SERVO4  (via drill 0.3)
  Top 0.152: 24.21,10.13 IC1.25
  Top 0.254: v22.06,10.28 22.21,10.13 24.21,10.13
  Bottom 0.254: v22.06,10.28 22.21,10.13 23.43,10.13 24.65,11.35 37,11.35 40.96,7.39 53.15,7.39 53.76,8 53.76,18.51 SERVO4.1 57.57,22.32
SERVO5  (via drill 0.3)
  Top 0.254: IC1.26 26.26,9.61 v26.94,10.28
  Bottom 0.254: v26.94,10.28 27.55,10.89 36.84,10.89 40.8,6.93 53.3,6.93 54.22,7.84 54.22,16.43 SERVO5.1 57.57,19.83
SERVO6  (via drill 0.3)
  Top 0.254: v30.59,10.28 30.59,17.14 28.65,19.08 IC1.7
  Bottom 0.152: SERVO6.1 57.57,17.29
  Bottom 0.254: v30.59,10.28 36.84,10.28 40.65,6.47 53.45,6.47 54.67,7.69 54.67,14.35 SERVO6.1
SERVO7  (via drill 0.3)
  Top 0.254: v18.25,9.82 18.4,9.98 18.4,14.24 19.24,15.08 IC1.15
  Bottom 0.254: v18.25,9.82 19.93,9.82 20.08,9.67 36.84,9.67 40.5,6.01 53.61,6.01 55.13,7.54 55.13,12.26 SERVO7.1
SERVO8  (via drill 0.3)
  Top 0.152: 24.23,14.55 IC1.16
  Top 0.254: v18.86,9.22 18.86,13.94 19.47,14.55 24.23,14.55
  Bottom 0.152: 57.42,11.81 57.42,11.96 57.57,12.11 SERVO8.1
  Bottom 0.254: v18.86,9.22 36.69,9.22 40.35,5.56 53.76,5.56 55.59,7.39 55.59,10.74 57.06,12.21
  Bottom 0.305: 57.06,12.21 SERVO8.1
SERVO9  (via drill 0.3)
  Top 0.152: IC1.17
  Top 0.254: IC1.17 19.77,14.09 19.47,13.79 19.47,10.28 20.23,9.52 21.91,9.52 22.82,8.61 v22.82,8
  Bottom 0.254: v22.82,8 33.34,8 35.32,6.01 35.32,5.1 35.62,4.8 53.61,4.8 56.05,7.23 56.05,8.1 SERVO9.1 57.57,9.62
SERVO10  (via drill 0.3)
  Top 0.254: v33.95,6.17 33.26,6.85 IC1.40
  Bottom 0.254: SERVO10.1 55.74,5.25 55.74,4.49 55.44,4.19 35.47,4.19 34.4,5.25 34.4,5.71 v33.95,6.17
SERVO11  (via drill 0.3)
  Top 0.152: 32.73,8.05 IC1.39
  Top 0.254: 32.73,8.05 32.73,6.47 v33.03,6.17
  Bottom 0.254: SERVO11.1 56.91,3.73 35.17,3.73 33.95,4.95 33.95,5.25 v33.03,6.17
SERVO12  (via drill 0.3)
  Top 0.254: v33.03,5.1 32.26,5.87 IC1.38
  Bottom 0.254: SERVO12.1 56.55,3.27 34.86,3.27 v33.03,5.1
SS_CSPS  (via drill 0.3)
  Top 0.254: IC1.19 23.03,13.08 v22.52,13.48
  Bottom 0.254: JP1.3 17.23,16.02 20.23,13.03 21.91,13.03 v22.52,13.48
SUPPLY
  Bottom 0.508: SUPPLY.1 18.71,24.56 18.71,20.95 20.23,19.43 37.3,19.43 37.91,18.82 37.91,14.85 38.27,14.5 SJ1.3
SW1
  Top 0.152: 43.34,19.88 SW1.2
  Top 0.254: 43.34,19.88 43.34,21.62 42.02,22.93 39.74,22.93 33.49,16.68 33.49,14.7 34.11,14.08 IC1.59
TXD0  (via drill 0.3)
  Top 0.152: 24.24,21.1 IC1.3
  Top 0.254: v10.63,21.56 13.98,24.91 19.16,24.91 20.23,23.85 22.06,23.85 22.82,23.08 22.82,21.56 23.28,21.1 24.24,21.1
  Bottom 0.254: v10.63,21.56 10.36,21.81 UART0.2
TXD1  (via drill 0.3)
  Top 0.254: IC1.46 36.23,4.64 36.23,3.73 | 36.23,3.73 36.23,3.58 | v34.4,1.29 36.23,3.12 36.23,3.73
  Bottom 0.254: v34.4,1.29 34.1,0.99 19.32,0.99 18.4,1.9 8.95,1.9 5.79,5.07 UART1.2
V+  (via drill 0.3)
  Top 0.61: 53.4,9.82 53.4,17.7 55.13,19.43 55.13,29.94 SERVO_SUPPLYL.2 | SERVO_SUPPLYR.2 53.4,3.73 53.4,9.82 | 53.4,9.82 53.4,9.06 42.79,9.06 42.48,9.37 v42.48,10.28 v41.72,11.04
  Bottom 0.61: SJ1.1 41.72,13.56 v41.72,11.04 42.45,10.31 v42.48,10.28
VERF_EXTERN
  Bottom 0.305: JP2.2 20.69,28.57 22.82,28.57 23.28,28.11 23.28,26.74 24.35,25.67 24.35,24.3 25.26,23.39 SJ2.2
XTAL1
  Top 0.152: 30.29,8.05 IC1.34 | 28.54,4.57 28.84,4.27
  Top 0.254: 28.84,4.27 C2.1 | 30.29,8.05 30.29,7.11 Q1.3
  Top 0.508: Q1.3 28.54,4.57
XTAL2
  Top 0.152: 19.95,3.58 19.93,3.58
  Top 0.254: C1.1 19.93,5.57 19.93,3.58 | 19.95,3.58 Q1.1 22.84,2.07 26.63,5.86 28.46,5.86 29.76,7.16 IC1.33

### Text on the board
tNames: AR7212 1.0 | 2009_09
